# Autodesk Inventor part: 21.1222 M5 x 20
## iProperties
Created: 2006-02
Part Number: 21.1222 M5 x 20
Material: Steel, Mild
Description: Cylinder Head Cap Screw
Document SubType Name: Modeling
Standard: DIN 7984
Designer: Andy Moles
Standards Organization: DIN
Language: en-US
Size Designation: M5 x 20
Categories: <MemberInstance><Categories><Category DisplayName="Fasteners" InternalName="e4da775c-781d-43d5-af7c-5136215cf5a6" Mnemonic="FSTN"><Category DisplayName="Bolts"
Density: 7.86 g/cm^3
Mass: 4.43338 g
Surface Area: 5.40621 cm^2
Volume: 0.564044 cm^3
Author: Andy Moles
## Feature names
1. Body [Revolution]
2. Slot [Extrusion]
3. Fillet1
4. Chamfer1
